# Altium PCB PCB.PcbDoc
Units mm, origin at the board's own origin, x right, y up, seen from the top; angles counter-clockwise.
Board outline 121 x 67.5 mm, 2 copper layers (Top Layer, Bottom Layer), stack 1.57 mm thick; 45 components, 32 nets, 182 pads, 30 vias.
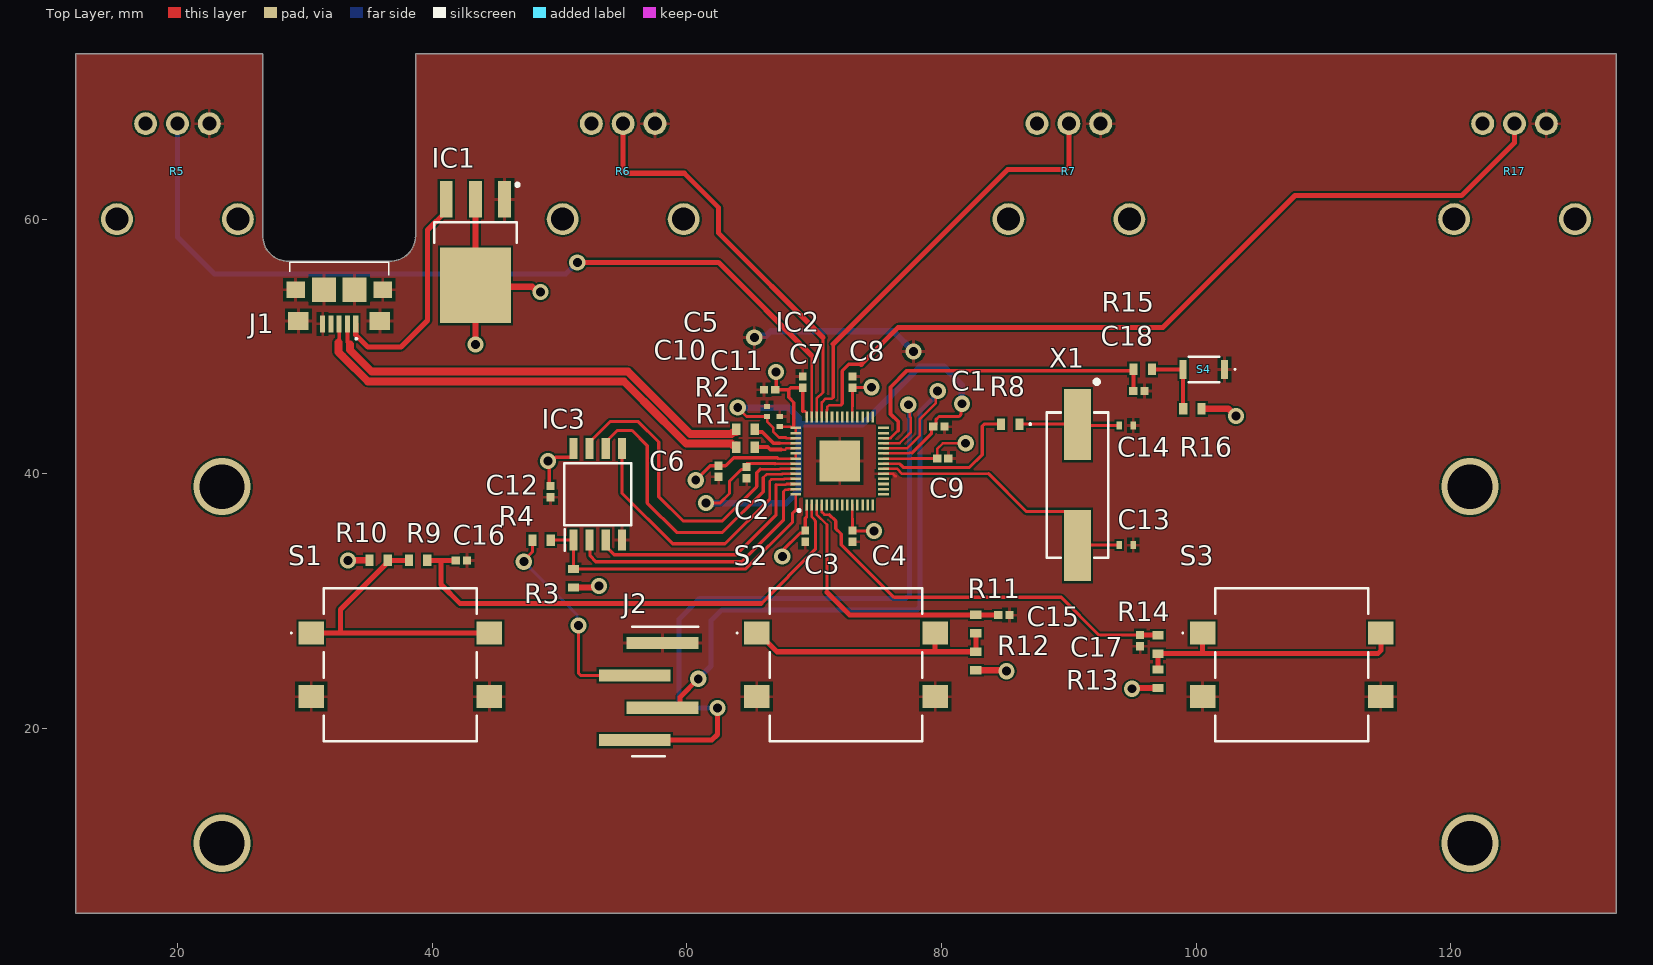
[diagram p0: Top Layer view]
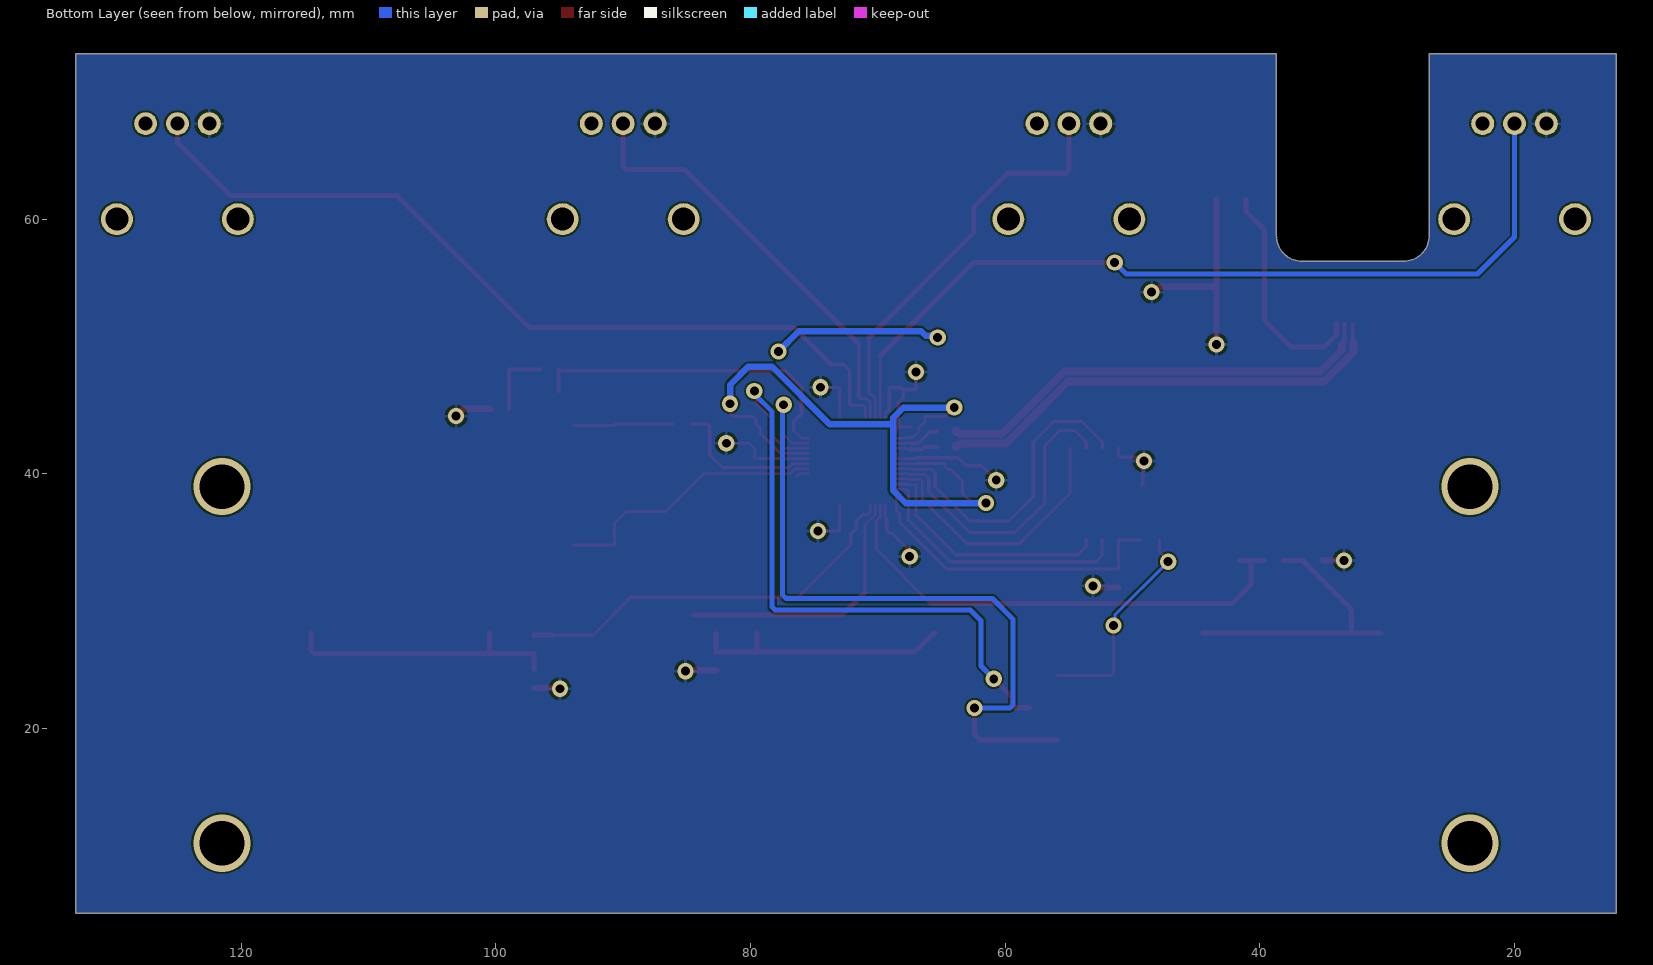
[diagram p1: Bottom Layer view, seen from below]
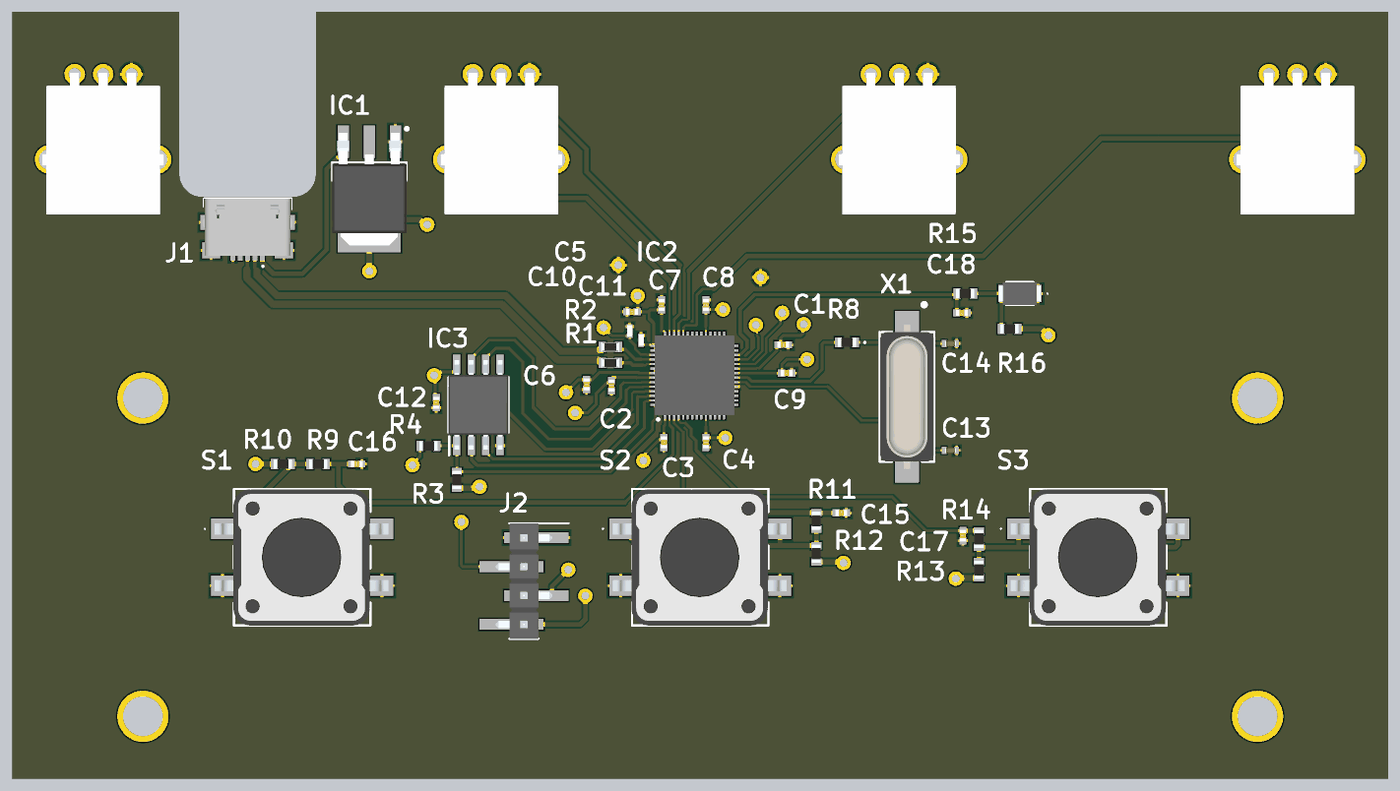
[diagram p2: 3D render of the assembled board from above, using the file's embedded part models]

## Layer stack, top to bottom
Top Solder: solder mask 0.0102, Solder Resist, Dk 3.5
Top Layer: signal copper 0.0356
Dielectric 1: core 1.4986, Core-043, Dk 4.3
Bottom Layer: signal copper 0.0356
Bottom Solder: solder mask 0.0102, Solder Resist, Dk 3.5

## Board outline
12,5.5 12,73 26.7,73 26.7,58.7 ccw(c28.7,58.7) 28.7,56.7 36.7,56.7 ccw(c36.7,58.7) 38.7,58.7 38.7,73 133,73 133,5.5

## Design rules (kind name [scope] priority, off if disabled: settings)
Clearance [All] p1: gap=0.15 ignorepadtopadclearanceinfootprint=TRUE
DiffPairsRouting "Diff USB" [All] p1: maxlimit=0.15 minlimit=0.15 mostfreqgap=0.15 toplayer_minwidth=0.3 toplayer_maxwidth=0.616 toplayer_prefwidth=0.616 bottomlayer_minwidth=0.616 bottomlayer_maxwidth=0.616 bottomlayer_prefwidth=0.616 impedanceprofiledriven=TRUE impedanceprofileid={1CA49ED8-FE3F-4F58-A43D-0094DE26AC73} impedanceprofilevalue=90.000000 maxuncoupledlength=12.7
DiffPairsRouting [All] p2: maxlimit=0.254 minlimit=0.254 mostfreqgap=0.254 toplayer_minwidth=0.381 toplayer_maxwidth=0.381 toplayer_prefwidth=0.381 bottomlayer_minwidth=0.381 bottomlayer_maxwidth=0.381 bottomlayer_prefwidth=0.381 maxuncoupledlength=12.7
Height [All] p1: minheight=0 maxheight=128 prefheight=12.7
MaxMinImpedance [InNetClass('Diff USB')] p1: minimum=85,00 maximum=95,00
PolygonConnect [All] p1: connectstyle=Relief reliefconductorwidth=0.254 reliefentries=4 polygonreliefangle="90 Angle" airgapwidth=0.254
RoutingVias [All] p1: holewidth=0.7 width=1.25 viastyle="Through Hole" minholewidth=0.7 minwidth=1.27 maxholewidth=3.5 maxwidth=4.85
SolderMaskExpansion [All] p1: expansion=0.102 istentingtop=FALSE
Width [All] p1: maxlimit=1 minlimit=0.2 preferedwidth=0.25 minimp=50.000000 maximp=50.000000 favimp=50.000000
28 further rules are at their usual default settings.

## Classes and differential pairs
differential pair class USB90Ohm: USB_D
net class "Diff USB": NetIC2_46 NetIC2_47 USB_D_N USB_D_P
differential pair USB_D: +USB_D_P -USB_D_N

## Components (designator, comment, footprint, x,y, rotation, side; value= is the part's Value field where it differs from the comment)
C1 "CGA2B1X7R1C104K050BC" CAPC1005X55N#1 79.8,43.7 r180 top
C2 "CGA2B1X7R1C104K050BC" CAPC1005X55N#1 64.7,40.1 r90 top
C3 "CGA2B1X7R1C104K050BC" CAPC1005X55N#1 69.3,35.1 r90 top
C4 "CGA2B1X7R1C104K050BC" CAPC1005X55N#1 73,35.1 r90 top
C5 "CGA2B1X7R1C104K050BC" CAPC1005X55N#1 66.5,46.6 r0 top
C6 "CGA2B1X7R1C104K050BC" CAPC1005X55N#1 62.5,40.2 r90 top
C7 "CGA2B1X7R1C104K050BC" CAPC1005X55N#1 69.1,47.2 r270 top
C8 "CGA2B1X7R1C104K050BC" CAPC1005X55N#1 73,47.2 r270 top
C9 "CGA2B1X7R1C104K050BC" CAPC1005X55N#1 80.1,41.2 r180 top
C10 "C1005X6S1C105K050BC" C1005_Commercial 66.3,44.9 r270 top
C11 "C1005X6S1C105K050BC" C1005_Commercial 67.3,44.1 r270 top
C12 "CGA2B1X7R1C104K050BC" CAPC1005X55N#1 49.296,38.6 r270 top
C13 "GJM1555C1H270FB01D" CAPC1005X55N#2 94.5,34.4 r180 top
C14 "GJM1555C1H270FB01D" CAPC1005X55N#2 94.5,43.8 r180 top
C15 "C0402C105K9PAC" CAPC1005X55N#1 84.9,28.9 r0 top
C16 "C0402C105K9PAC" CAPC1005X55N#1 42.3,33.2 r0 top
C17 "C0402C105K9PAC" CAPC1005X55N#1 95.6,26.9 r270 top
C18 "C0402C105K9PAC" CAPC1005X55N#1 95.5,46.5 r0 top
IC1 "NCP1117DT33T5G" TO229P990X238-4N 43.4,57.4 r270 top
IC2 "RPI_Chip_RP2040-10-10" QFN40P700X700X90-57N-D 72,41 r90 top
IC3 "W25Q128JVSIM" SOIC127P790X216-8N 53,38.4 r90 top
J1 "2174507-2" 21745072 32.7,54.1 r180 top
J2 "61000418321" HUSRSP4W64P254_1016X254X854P 57,22.9 r270 top
R1 "ERA3AHD27R4V" ERA3A_(0603) 64.6,42.1 r180 top
R2 "ERA3AHD27R4V" ERA3A_(0603) 64.6,43.5 r180 top
R3 "ERJ-3EKF1001V" ERJ3EK_(0603) 51.1,31.8 r270 top
R4 "ERJ-3EKF1001V" ERJ3EK_(0603) 48.6,34.8 r0 top
R5 "Pot 10k" P0915NFC15BR10K 20,60 r180 top
R6 "Pot 10k" P0915NFC15BR10K 55,60 r180 top
R7 "Pot 10k" P0915NFC15BR10K 90,60 r180 top
R8 "ERJ-3EKF1001V" ERJ3EK_(0603) 85.4,43.9 r180 top
R9 "10k" ERJ3EK_(0603) 38.9,33.2 r0 top
R10 "1k" ERJ3EK_(0603) 35.8,33.2 r180 top
R11 "10k" ERJ3EK_(0603) 82.7,28.2 r90 top
R12 "ERJ-3EKF1001V" ERJ3EK_(0603) 82.7,25.3 r270 top
R13 "1k" ERJ3EK_(0603) 97,23.9 r270 top
R14 "10k" ERJ3EK_(0603) 97,26.6 r90 top
R15 "10k" ERJ3EK_(0603) 95.8,48.2 r180 top
R16 "1k" ERJ3EK_(0603) 99.7,45.1 r0 top
R17 "Pot 10k" P0915NFC15BR10K 125,60 r180 top
S1 "430172043816" 430172043816 37.5,25 r0 top
S2 "430172043816" 430172043816 72.5,25 r0 top
S3 "430172043816" 430172043816 107.5,25 r0 top
S4 "TS19-32-06-BK-70-1-SMT-TR-67" TS193206BK701SMTTR67 100.6,48.2 r180 top
X1 "ABLS-12.000MHZ-B4-T" HC/49US-(AT49)_1 90.678,39.116 r270 top

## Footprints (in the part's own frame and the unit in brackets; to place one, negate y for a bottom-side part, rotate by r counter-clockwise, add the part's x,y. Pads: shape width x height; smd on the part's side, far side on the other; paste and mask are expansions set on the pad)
21745072 [mm]
  rect 0.4x1.35 smd: 1(-1.3,2.325) 2(-0.65,2.325) 3(0,2.325) 4(0.65,2.325) 5(1.3,2.325)
  rect 1.45x1.3 smd: MP1(-3.425,-0.35) MP1(3.425,-0.35)
  rect 1.6x1.4 smd: MP1(-3.2,2.1) MP1(3.2,2.1)
  rect 1.9x1.9 smd: MP1(-1.2,-0.35) MP1(1.2,-0.35)
  silkscreen extent -3.9,-2.5 3.9,3.55, body extent -3.9,-2.43 3.9,2.57, height 2.7
430172043816 [mm]
  rect 2x1.8 smd: 1(-7,2.5) 2(7,2.5) 3(-7,-2.5) 4(7,-2.5)
  silkscreen extent -8.6,-6 6,6, body extent -7.7,-6.02 7.6,5.98, height 4.28
C1005_Commercial [mm]
  rect 0.4x0.5 smd: 1(-0.4,0) 2(0.4,0)
  body extent -0.51,-0.25 0.49,0.25, height 0.5
CAPC1005X55N#1 [mm]
  rect 0.65x0.62 smd: 1(-0.44,0) 2(0.44,0)
  body extent -0.52,-0.28 0.53,0.27, height 0.55
CAPC1005X55N#2 [mm]
  rect 0.42x0.62 smd: 1(-0.55,0) 2(0.55,0)
  body extent -0.5,-0.25 0.5,0.25, height 0.55
ERA3A_(0603) [mm]
  rect 0.65x0.9 smd: 1(-0.725,0) 2(0.725,0)
  body extent -0.8,-0.4 0.8,0.4, height 0.45
ERJ3EK_(0603) [mm]
  rect 0.65x0.9 smd: 1(-0.725,0) 2(0.725,0)
  body extent -0.8,-0.4 0.8,0.4, height 0.45
HC/49US-(AT49)_1 [mm]
  rect 5.6x2.1 smd: 1(-4.75,0) 2(4.75,0)
  silkscreen extent -8.23,-2.4 5.7,2.4, body extent -6.35,-2.35 6.35,2.35, height 4.2
HUSRSP4W64P254_1016X254X854P [mm]
  rect 0.96x5.64 smd: 1(-3.81,1.09) 2(-1.27,-1.09) 3(1.27,1.09) 4(3.81,-1.09)
  silkscreen extent -5.08,-1.27 5.08,3.91, body extent -5.08,-2.5 5.08,2.5, height 9.3
P0915NFC15BR10K [mm]
  round 1.8 hole 1.1: 1(-2.5,-7.5) 2(0,-7.5) 3(2.5,-7.5)
  round 2.5 hole 1.8: 4(-4.75,0) 4(4.75,0)
  body extent -5.35,-7.6 5.35,4.85, height 30
QFN40P700X700X90-57N-D [mm]
  rect 0.85x0.2 smd: 1(-3.45,2.6) 2(-3.45,2.2) 3(-3.45,1.8) 4(-3.45,1.4) 5(-3.45,1) 6(-3.45,0.6) 7(-3.45,0.2) 8(-3.45,-0.2) 9(-3.45,-0.6) 10(-3.45,-1) 11(-3.45,-1.4) 12(-3.45,-1.8) 13(-3.45,-2.2) 14(-3.45,-2.6) 29(3.45,-2.6) 30(3.45,-2.2) 31(3.45,-1.8) 32(3.45,-1.4) 33(3.45,-1) 34(3.45,-0.6) 35(3.45,-0.2) 36(3.45,0.2) 37(3.45,0.6) 38(3.45,1) 39(3.45,1.4) 40(3.45,1.8) 41(3.45,2.2) 42(3.45,2.6)
  rect 0.2x0.85 smd: 15(-2.6,-3.45) 16(-2.2,-3.45) 17(-1.8,-3.45) 18(-1.4,-3.45) 19(-1,-3.45) 20(-0.6,-3.45) 21(-0.2,-3.45) 22(0.2,-3.45) 23(0.6,-3.45) 24(1,-3.45) 25(1.4,-3.45) 26(1.8,-3.45) 27(2.2,-3.45) 28(2.6,-3.45) 43(2.6,3.45) 44(2.2,3.45) 45(1.8,3.45) 46(1.4,3.45) 47(1,3.45) 48(0.6,3.45) 49(0.2,3.45) 50(-0.2,3.45) 51(-0.6,3.45) 52(-1,3.45) 53(-1.4,3.45) 54(-1.8,3.45) 55(-2.2,3.45) 56(-2.6,3.45)
  rect 3.2x3.2 smd: 57(0,0)
  silkscreen extent -3.97,3.1 -3.78,3.3, body extent -3.55,-3.55 3.55,3.55, height 0.9
SOIC127P790X216-8N [mm]
  rect 1.65x0.65 smd: 1(-3.6,1.905) 2(-3.6,0.635) 3(-3.6,-0.635) 4(-3.6,-1.905) 5(3.6,-1.905) 6(3.6,-0.635) 7(3.6,0.635) 8(3.6,1.905)
  silkscreen extent -4.43,-2.64 2.42,2.64, body extent -3.95,-2.64 3.95,2.64, height 2.16
TO229P990X238-4N [mm]
  rect 2.85x1 smd: 1(-4.15,2.29) 2(-4.15,0) 3(-4.15,-2.29)
  rect 5.95x5.55 smd: 2(2.6,0)
  silkscreen extent -5.42,-3.25 -0.75,3.43, body extent -4.96,-3.27 4.96,3.27, height 2.39
TS193206BK701SMTTR67 [mm]
  rect 0.55x1.5 smd: 1(-1.625,0) 2(1.625,0)
  silkscreen extent -2.5,-1 1.2,1, body extent -1.85,-1 1.85,1, height 0.75

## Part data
C1 C2 C3 C4 C5 C6 C7 C8 C9 C12: "Capacitor 100nF 16V", Manufacturer_Name=TDK, Mouser Part Number=810-CGA2B1X7R1C104K
C10 C11: "Capacitor 0402 1µF 16V", Manufacturer_Name=TDK, Mouser Part Number=810-C1005X6S1C105K
C13 C14: "Capacitor 27pF 50V", Manufacturer_Name="Murata Electronics", Mouser Part Number=81-GJM1555C1H270FB1D
C15 C16 C17 C18: "Capacitor 1µF 6V3 0402", Manufacturer_Name=KEMET, Mouser Part Number=80-C0402C105K9PAC
IC1: "LDO 3V3 out", Manufacturer_Name=onsemi, Mouser Part Number=863-NCP1117DT33T5G
IC2: "RP2040 MCU", Manufacturer_Name=RASPBERRY-PI, Manufacturer_Part_Number="RPI Chip RP2040-10-10", Mouser Part Number=358-RP2040CHIP-10-10
IC3: "128 SPI Nor flash", Manufacturer_Name=Winbond, Mouser Part Number=454-W25Q128JVSIM
J1: "Micro USB Connector", Manufacturer_Name="TE Connectivity", Mouser Part Number=571-2174507-2
J2: "Connector", Manufacturer_Name="Wurth Elektronik"
R1 R2: "Resistor 0603 27.4Ohm", Manufacturer_Name=Panasonic
R3 R4 R8 R12: "Resistor 1k 0603", Manufacturer_Name=Panasonic, Mouser Part Number=667-ERJ-3EKF1001V
R5 R6 R7 R17: library part P0915N-FC15BR10K, "POT 10k", Manufacturer_Name="TT Electronics", Mouser Part Number=858-P0915N-FC15BR10K
R9 R11 R14 R15: library part ERJ-3EKF1001V, "Resistor 10k 0603", Manufacturer_Name=Panasonic, Mouser Part Number=667-ERJ-3EKF1001V
R10 R13 R16: library part ERJ-3EKF1001V, "Resistor 1k 0603", Manufacturer_Name=Panasonic, Mouser Part Number=667-ERJ-3EKF1001V
S1 S2 S3: "Switch", Manufacturer_Name="Wurth Elektronik", Mouser Part Number=710-430172043816
S4: "Switch", Manufacturer_Name="CUI Inc.", Mouser Part Number=179-TS193206BK701SM
X1: "Crystal oscillator", Manufacturer_Name=ABRACON, Mouser Part Number=815-ABLS-12.0M-T

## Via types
v1: diameter 1.27, hole 0.7, Top Layer to Bottom Layer, 26 vias
v2: diameter 4.5, hole 3.5, Top Layer to Bottom Layer, 4 vias

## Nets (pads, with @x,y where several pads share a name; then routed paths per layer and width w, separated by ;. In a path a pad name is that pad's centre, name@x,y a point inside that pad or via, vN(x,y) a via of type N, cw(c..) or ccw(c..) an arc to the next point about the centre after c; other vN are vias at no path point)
1V1: C1.2 C2.2 C10.2 IC2.23 IC2.45 IC2.50 | length 58.8
  Top Layer w0.2: v1(64,45.2) 64.7,44.5 C10.2 66.3,44.1 66.8,43.6 66.8,43.3 67.25,42.85 67.763,42.85 67.813,42.8 IC2.45 ; 66.927,40.786 66.941,40.8 67.312,40.8 IC2.50 ; IC2.23 77.449,41.6 77.466,41.6 77.516,41.65 77.7,41.65
  Top Layer w0.25: v1(61.5,37.7) 62.6,37.7 63.355,38.455 63.355,39.41 64.285,40.34 64.515,40.34 64.7,40.525 C2.2 ; 77.7,41.65 79.222,43.172 79.222,43.562 C1.2 79.375,43.7 79.56,43.885 79.56,44.26 79.8,44.5 81.379,44.5 81.525,44.646 81.525,45.425 v1(81.6,45.5)
  Top Layer w0.254: C2.2@64.7,40.759 64.754,40.813 66.9,40.813 66.927,40.786
  Bottom Layer w0.5: v1(61.5,37.7) 67.807,37.7 68.8,38.693 68.8,43.9 ; v1(64,45.2) 68.007,45.2 68.8,44.407 68.8,43.9 ; v1(81.6,45.5) 81.6,47 80.2,48.4 78.3,48.4 73.8,43.9 68.8,43.9
3V3: C3.2 C4.2 C5.2 C6.2 C7.2 C8.2 C9.2 C11.2 C12.1 IC1.2 IC2.1 IC2.10 IC2.22 IC2.33 IC2.42 IC2.43 IC2.44 IC2.48 IC2.49 IC3.8 R3.2 R5.3 R6.3 R7.3 R10.2 R12.2 R13.2 R16.2 R17.3 | length 72.1
  Top Layer w0.2: 67.135,41.227 67.135,41.213 67.175,41.2 IC2.49 IC2.48 ; C11.2@67.4,43.7 68.125,43.7 68.225,43.6 68.4,43.6 IC2.43 IC2.44 ; 69.1,44.9 69.283,44.9 69.4,44.783 IC2.42 ; 69.375,36.6 69.4,36.6 IC2.1 ; 73,36.5 IC2.10 ; IC2.33 73,45.3 ; IC2.22 77.65,41.2 ; C9.2@79.675,41.2 79.675,41.975 80.1,42.4 v1(81.9,42.4)
  Top Layer w0.25: C12.1 49.198,39.138 49.198,40.902 v1(49.1,41) 49.376,41 49.676,41.3 50.895,41.3 51.095,41.5 IC3.8 ; v1(67,48) 67.02,47.98 67.02,46.6 68,46.6 ; v1(67.5,33.5) 67.5,33.955 68.885,35.34 69.115,35.34 69.3,35.525 C3.2 69.3,36.525 69.375,36.6 ; IC2.43@68.4,43.625 68.4,45.6 68,46 68,46.614 68.146,46.76 C7.2 69.1,44.9 ; 73,36.5 C4.2 73.02,35.52 74.68,35.52 v1(74.7,35.5) ; 73,45.3 C8.2 73.02,46.78 74.48,46.78 v1(74.5,46.8) ; 77.65,41.2 C9.2@79.36,41.2
  Top Layer w0.254: v1(60.7,39.5) 61.826,40.626 63.042,40.626 63.683,41.267 67.095,41.267 67.135,41.227
  Top Layer w0.5: v1(33.4,33.2) R10.2 ; IC1.2@43.4,61.55 IC1.2@43.4,54.8 ; v1(43.409,50.162) 43.4,50.172 IC1.2@43.4,54.8 ; v1(48.5,54.265) 48.292,54.265 47.857,54.7 43.5,54.7 IC1.2@43.4,54.8 ; R3.2 52.975,31.075 v1(53.1,31.2) ; R12.2 85.025,24.575 v1(85.1,24.5) ; v1(94.968,23.118) 95.024,23.175 R13.2 ; R16.2 102.541,45.1 v1(103.113,44.527)
5V: IC1.3 J1.1 | length 17.9
  Top Layer w0.4: J1.1 34,50.9 34.951,49.949 37.549,49.949 39.638,52.038 39.638,59.153 41.11,60.625 IC1.3
B1: C16.1 IC2.2 R9.2 | length 39.3
  Top Layer w0.2: IC2.2 69.8,36.801 69.8,36.634 70.063,36.371 70.063,36.333
  Top Layer w0.254: 40.635,33.2 40.7,33.135 ; 65.833,29.8 70.1,34.067 70.1,36.296 70.063,36.333
  Top Layer w0.4: R9.2 40.635,33.2 C16.1@41.645,33.2 ; 40.7,33.135 40.7,31.3 42.2,29.8 65.833,29.8
B2: C15.1 IC2.3 R11.2 | length 21.4
  Top Layer w0.2: IC2.3 70.2,36.8 71,36
  Top Layer w0.254: 71,30.7 71,36
  Top Layer w0.4: 71,30.7 72.775,28.925 R11.2 82.712,28.912 84.448,28.912 C15.1
B3: C17.1 IC2.4 R14.2 | length 31.8
  Top Layer w0.2: IC2.4 70.6,37.001 70.801,36.8 71.2,36.8
  Top Layer w0.254: 71.2,36.8 71.7,36.3 71.7,35.7 72.127,35.273 72.127,34.435 76.263,30.3 89.4,30.3 92.367,27.333 C17.1@95.607,27.333
  Top Layer w0.4: C17.1@95.607,27.333 96.992,27.333 R14.2
GND: C1.1 C2.1 C3.1 C4.1 C5.1 C6.1 C7.1 C8.1 C9.1 C10.1 C11.1 C12.2 C13.1 C14.1 C15.2 C16.2 C17.2 C18.2 IC1.1 IC2.19 IC2.57 IC3.4 J1.5 J1.MP1 J2.1 R5.1 R6.1 R7.1 R17.1 S1.3 S1.4 S2.3 S2.4 S3.3 S3.4 S4.1 | length 14.4
  Top Layer w0.2: IC2.19 76.2,40 76.4,39.8
  Bottom Layer w0.5: v1(65.3,50.7) 65.447,50.847 66.247,50.847 66.6,51.2 76.2,51.2 v1(77.8,49.6)
NetC14_2: C14.2 R8.1 X1.1 | length 7.9
  Top Layer w0.25: R8.1 90.644,43.9 X1.1 90.744,43.8 C14.2
NetIC2_46: IC2.46 R2.1 | length 3.6
  Top Layer w0.2: 67.3,42.4 IC2.46
  Top Layer w0.3: R2.1@65.325,43.4 65.45,43.275 65.925,43.275 66.8,42.4 67.3,42.4
NetIC2_47: IC2.47 R1.1 | length 3.3
  Top Layer w0.2: 67.4,41.9 67.725,41.9 67.825,42 IC2.47
  Top Layer w0.3: R1.1 66.35,42.1 66.55,41.9 67.4,41.9
NetJ2_2: J2.2 R4.1 | length 17
  Top Layer w0.254: v1(47.2,33.1) 47.2,33.187 47.875,33.862 R4.1 ; v1(51.5,28.1) 51.5,24.319 51.649,24.17 J2.2
  Bottom Layer w0.254: v1(47.2,33.1) 51.386,28.914 51.386,28.214 v1(51.5,28.1)
NetR9_1: R9.1 R10.1 S1.1 S1.2 | length 22.9
  Top Layer w0.4: S1.1 32.8,27.5 ; R9.1 R10.1 36.525,33.075 32.8,29.35 32.8,27.5 ; S1.2 32.8,27.5
NetR11_1: R11.1 R12.1 S2.1 S2.2 | length 20.7
  Top Layer w0.4: S2.1 65.6,27.5 67.075,26.025 79.5,26.025 ; S2.2 79.5,26.025 ; R11.1 R12.1 79.5,26.025
NetR13_1: R13.1 R14.1 S3.1 S3.2 | length 21.9
  Top Layer w0.4: R13.1 R14.1 100.5,25.875 ; S3.1 100.5,25.875 ; S3.2 114.5,26.109 114.266,25.875 100.5,25.875
NetR15_1: R15.1 R16.1 S4.2 | length 5.6
  Top Layer w0.3: R15.1 S4.2 R16.1
Pot1: IC2.38 R17.2 | length 66.4
  Top Layer w0.2: IC2.38 71,45.009 71.025,45.034 71.025,45.234 71.191,45.4 72.083,45.4
  Top Layer w0.254: 72.083,45.4 72.2,45.517 72.2,48.083 72.717,48.6 73.7,48.6
  Top Layer w0.4: 73.7,48.6 76.6,51.5 97.4,51.5 107.75,61.85 120.85,61.85 125,66 R17.2
Pot2: IC2.39 R7.2 | length 34
  Top Layer w0.2: IC2.39 70.6,45.6 70.9,45.9 71.383,45.9 71.5,46.017
  Top Layer w0.254: 71.5,46.017 71.5,50.2
  Top Layer w0.4: 71.5,50.2 85.2,63.9 89.766,63.9 90,64.134 R7.2
Pot3: IC2.40 R6.2 | length 32.4
  Top Layer w0.2: IC2.40 70.2,45.9 70.7,46.4
  Top Layer w0.254: 70.7,46.4 70.7,50.7
  Top Layer w0.4: R6.2 55,63.834 55.234,63.6 59.8,63.6 62.5,60.9 62.5,58.9 70.7,50.7
Pot4: IC2.41 R5.2 | length 68.1
  Top Layer w0.2: IC2.41 69.8,49.3
  Top Layer w0.4: v1(51.4,56.6) 62.5,56.6 69.8,49.3
  Bottom Layer w0.4: R5.2 20,58.6 22.9,55.7 50.5,55.7 v1(51.4,56.6)
QSPI_CLK: IC2.52 IC3.6 | length 24.3
  Top Layer w0.2: 66,39.7 66.259,39.959 67.463,39.959 67.504,40 67.643,40 IC2.52
  Top Layer w0.254: IC3.6 53.635,42.5 54.535,43.4 55.7,43.4 56.9,42.2 56.9,37.7 59.2,35.4 62.8,35.4 66,38.6 66,39.7
QSPI_SD0: IC2.53 IC3.5 | length 21.7
  Top Layer w0.2: 66.5,38 66.5,39.415 66.644,39.559 67.628,39.559 67.669,39.6 67.809,39.6 IC2.53
  Top Layer w0.254: IC3.5 54.905,38.495 58.9,34.5 63,34.5 66.5,38
QSPI_SD1: IC2.55 IC3.2 | length 21.3
  Top Layer w0.2: 67.6,38.615 67.717,38.732 67.933,38.732 68.001,38.8 IC2.55
  Top Layer w0.254: IC3.2 52.4,34.765 52.4,33.549 52.849,33.1 64.3,33.1 67.6,36.4 67.6,38.615
QSPI_SD2: IC2.54 IC3.3 | length 19.4
  Top Layer w0.2: 67,39.132 67.767,39.132 67.835,39.2 67.974,39.2 IC2.54
  Top Layer w0.254: IC3.3 53.635,34.3 54.287,33.648 63.896,33.648 67,36.752 67,39.132
QSPI_SD3: IC2.51 IC3.7 | length 25.4
  Top Layer w0.2: 65.759,40.359 67.297,40.359 67.338,40.4 67.477,40.4 IC2.51
  Top Layer w0.254: IC3.7 52.365,42.5 53.965,44.1 56.2,44.1 57.8,42.5 57.8,38.2 59.7,36.3 62.804,36.3 65.5,38.996 65.5,40.1 65.759,40.359
QSPI_SS: IC2.56 IC3.1 R3.1 R4.2 | length 25.1
  Top Layer w0.2: 68.55,37.15 IC2.56
  Top Layer w0.254: R4.2 IC3.1 R3.1@51.095,32.53 ; R3.1 R3.1@51.095,32.53 ; 68.55,37.15 68.3,36.9 68.3,36.2 64.63,32.53 R3.1@51.095,32.53
RUN: C18.1 IC2.26 R15.2 | length 26.4
  Top Layer w0.2: IC2.26 75.999,42.8 76.6,43.401
  Top Layer w0.3: 76.6,43.401 76.6,44.1 76,44.7 76,46.8 77.3,48.1 94.975,48.1 R15.2@95.067,48.192 ; C18.1 95.067,46.507 R15.2@95.067,48.192 ; R15.2 R15.2@95.067,48.192
SWCLK: IC2.24 J2.3 | length 50.8
  Top Layer w0.2: IC2.24 77.3,42 78.3,43 78.3,44.3 79.565,45.565 79.565,46.365 v1(79.7,46.5)
  Top Layer w0.4: J2.3 59.196,21.63 59.476,21.91 59.476,22.476 v1(60.9,23.9)
  Bottom Layer w0.4: v1(60.9,23.9) 61.9,24.9 61.9,28.466 62.734,29.3 78.066,29.3 78.3,29.534 78.3,44.865 79.7,46.265 v1(79.7,46.5)
SWDIO: IC2.25 J2.4 | length 57.2
  Top Layer w0.2: IC2.25 76.7,42.4 77.6,43.3 77.6,44.388 77.5,44.488 77.5,45.317 v1(77.394,45.423)
  Top Layer w0.4: J2.4 61.956,19.09 62.4,19.534 v1(62.4,21.6)
  Bottom Layer w0.4: v1(62.4,21.6) 59.634,21.6 59.4,21.834 59.4,28.6 61,30.2 77.2,30.2 77.5,30.5 77.5,45.317 v1(77.394,45.423)
USB_D_N: J1.2 R2.2 | length 35.4
  Top Layer w0.2: 33.4,50.3 33.541,50.159
  Top Layer w0.3: J1.2 33.35,50.35 33.4,50.3
  Top Layer w0.616: 33.541,50.159 33.541,49.741 35.259,48.024 55.376,48.024 60.267,43.133 63.497,43.133 63.622,43.258 63.858,43.258 63.875,43.275 R2.2@63.875,43.4
USB_D_P: J1.3 R1.2 | length 36.6
  Top Layer w0.3: 32.634,50.3 32.7,50.366 J1.3
  Top Layer w0.616: 32.634,50.3 32.634,49.566 33,49.2 34.941,47.259 55.059,47.259 58.054,44.264 58.459,43.859 59.95,42.367 63.497,42.367 63.622,42.242 63.858,42.242 63.875,42.225 R1.2
XIN: C13.2 IC2.20 X1.2 | length 22
  Top Layer w0.2: IC2.20 76.5,40.4 76.9,40 83.7,40
  Top Layer w0.25: 83.7,40 86.659,37.041 89.753,37.041 90.678,36.116 X1.2 90.712,34.4 C13.2
XOUT: IC2.21 R8.2 | length 12.1
  Top Layer w0.2: IC2.21 76.701,40.8 76.801,40.701
  Top Layer w0.25: 76.801,40.701 77.001,40.5 82.2,40.5 83.2,41.5 83.2,43.754 83.346,43.9 R8.2
pads on no net: IC2.5 IC2.6 IC2.7 IC2.8 IC2.9 IC2.11 IC2.12 IC2.13 IC2.14 IC2.15 IC2.16 IC2.17 IC2.18 IC2.27 IC2.28 IC2.29 IC2.30 IC2.31 IC2.32 IC2.34 IC2.35 IC2.36 IC2.37 J1.4 R5.4 R6.4 R7.4 R17.4
copper on no net:
  other v2: 23.5,11 121.5,11 23.5,39 121.5,39

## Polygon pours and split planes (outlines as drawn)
3V3 on Bottom Layer "3V3_L02_P003" (solid, pour order 3): 12,5.5 12,73 26.7,73 26.7,58.7 ccw(c28.7,58.7) 28.7,56.7 36.7,56.7 ccw(c36.7,58.7) 38.7,58.7 38.7,73 133,73 133,5.5
GND on Top Layer "GND_L01_P002" (solid, remove dead copper, pour order 2): 12,5.5 12,73 26.7,73 26.7,58.7 ccw(c28.7,58.7) 28.7,56.7 36.7,56.7 ccw(c36.7,58.7) 38.7,58.7 38.7,73 133,73 133,5.5

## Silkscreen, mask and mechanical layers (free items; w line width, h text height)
Mechanical 1:
  circle w0.013: c23.5,11 r2
  circle w0.013: c121.5,11 r2
  circle w0.013: c121.5,39 r2
  circle w0.013: c23.5,39 r2
  lines w0.013: 12,5.5 133,5.5 133,73 38.7,73 38.7,58.7 cw(c36.7,58.7) 36.7,56.7 28.7,56.7 cw(c28.7,58.7) 26.7,58.7 26.7,73 12,73 12,5.5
